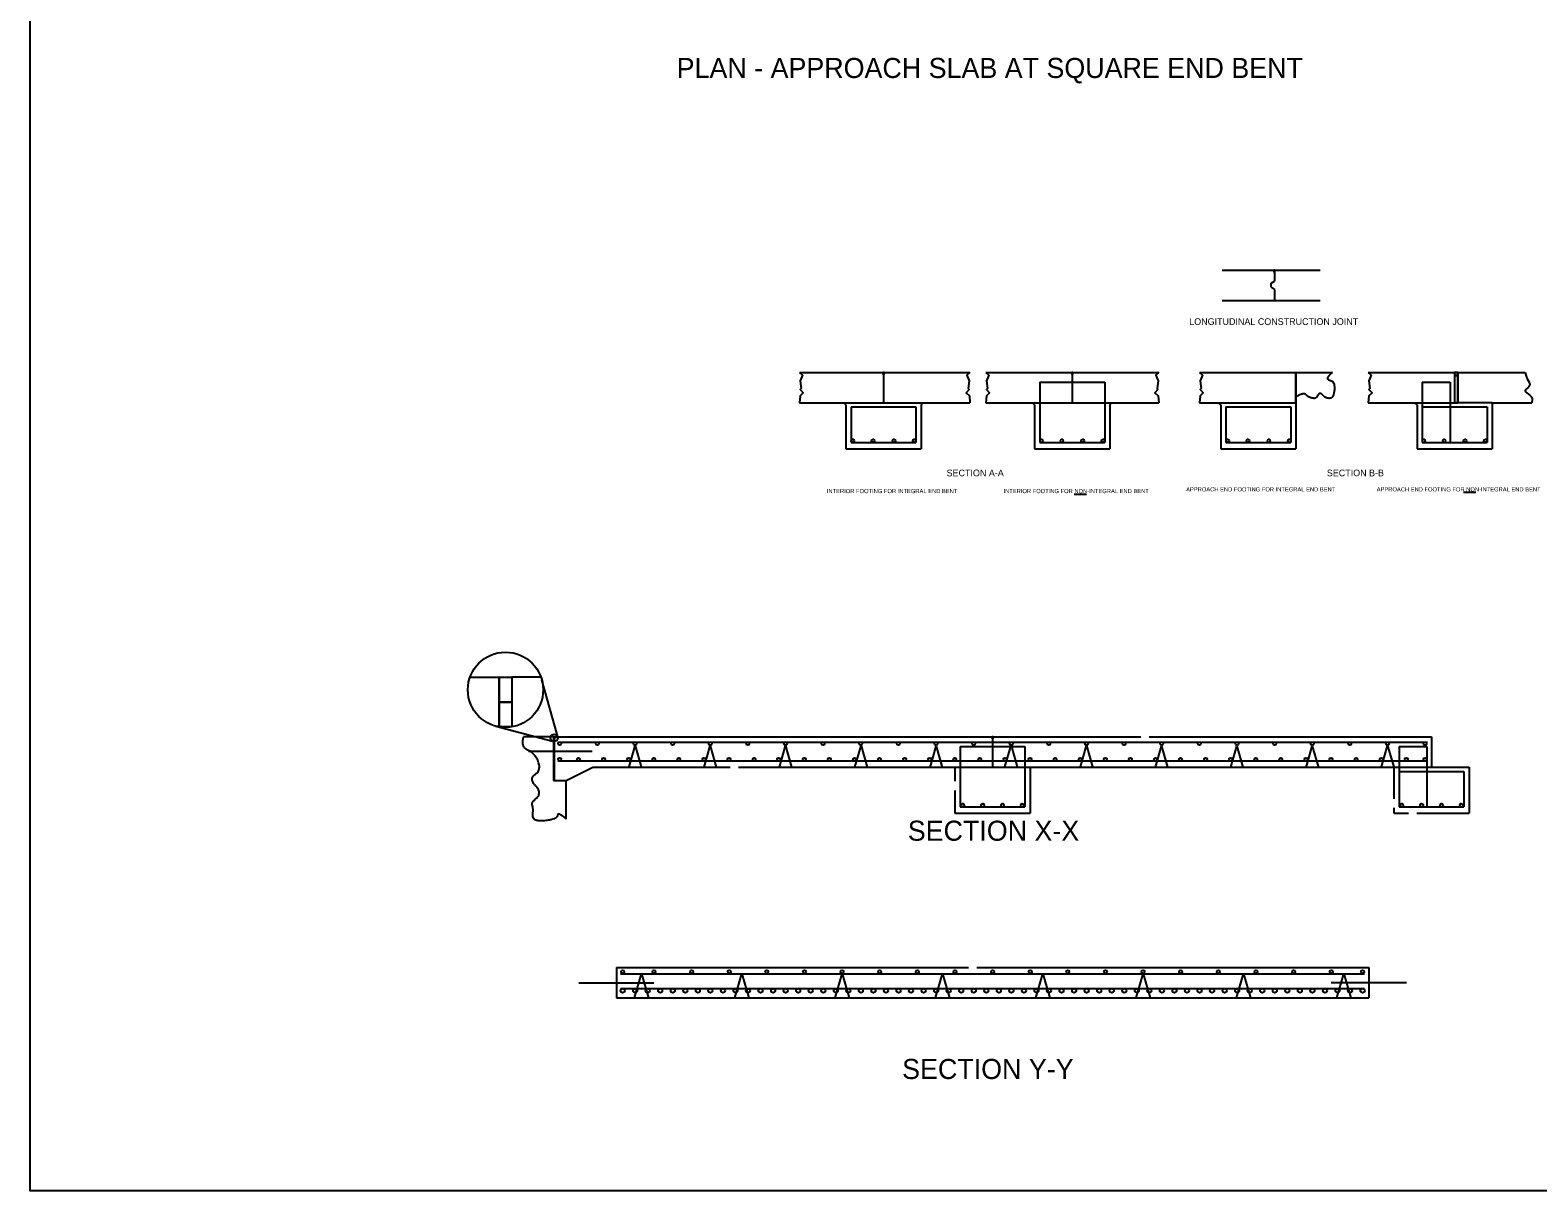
# Model space of a CAD drawing. Extents: x 1531 to 2925, y 1224 to 1658.
# Drawn here: x 2396.3 to 2456.4, y 1330.2 to 1376.5 of the extents above; entities that cross this region are included whole.
import ezdxf

# ---------------------------------------------------------------- set-up
doc = ezdxf.new("R2010")
doc.units = 0
for name, color, linetype in [('B_Boring Annot', 7, 'Continuous'), ('BD-EXIST-COSS', 7, 'Continuous'), ('BD-PROP-COSS', 7, 'Continuous'), ('BD-PROP-OSB', 7, 'Continuous'), ('D_FEMA A', 7, 'Continuous'), ('R_Anno_Text', 7, 'Continuous'), ('R_Draft', 7, 'Continuous'), ('R_Horz Alg', 7, 'Continuous'), ('R_Road Edge of Shoulder', 7, 'Continuous'), ('R_Road Edge of Travel', 7, 'Continuous'), ('R_ROW', 7, 'Continuous'), ('R_Survey Control', 7, 'Continuous'), ('R_Wall', 7, 'Continuous'), ('S_GAS_UTILITIES', 7, 'Continuous')]:
    doc.layers.add(name, color=color, linetype=linetype)

msp = doc.modelspace()

# ---------------------------------------------------------------- linework, layer by layer
at = {"layer": 'B_Boring Annot'}
for p, q in [((2413.853, 1350.708), (2415.017, 1350.708)), ((2415.017, 1350.708), (2415.017, 1348.729))]:
    msp.add_line(p, q, dxfattribs=at)
at = {"layer": 'BD-EXIST-COSS'}
for p, q in [((2436.57, 1362.472), (2439.154, 1362.472)), ((2436.57, 1362.472), (2436.57, 1360.068)), ((2439.154, 1362.472), (2439.154, 1360.068)), ((2451.815, 1362.472), (2452.925, 1362.472)), ((2451.815, 1362.472), (2451.815, 1360.066)), ((2452.925, 1362.472), (2452.925, 1360.066)), ((2429.044, 1361.485), (2431.628, 1361.485)), ((2429.044, 1361.485), (2429.044, 1360.068)), ((2431.628, 1361.485), (2431.628, 1360.068)), ((2443.99, 1361.485), (2446.573, 1361.485)), ((2443.99, 1361.485), (2443.99, 1360.068)), ((2446.573, 1361.485), (2446.573, 1360.068)), ((2451.815, 1361.485), (2454.398, 1361.485)), ((2451.815, 1361.485), (2451.815, 1360.068)), ((2454.398, 1361.485), (2454.398, 1360.068)), ((2429.044, 1360.068), (2431.628, 1360.068)), ((2436.57, 1360.068), (2439.154, 1360.068)), ((2443.99, 1360.068), (2446.573, 1360.068)), ((2451.815, 1360.068), (2454.398, 1360.068)), ((2417.352, 1348.123), (2452.019, 1348.123)), ((2433.394, 1347.943), (2435.977, 1347.943)), ((2433.394, 1347.943), (2433.394, 1345.539)), ((2435.977, 1347.943), (2435.977, 1345.539)), ((2450.894, 1347.943), (2452.004, 1347.943)), ((2450.894, 1347.943), (2450.894, 1345.537)), ((2452.004, 1347.943), (2452.004, 1345.537)), ((2417.352, 1347.373), (2452.019, 1347.373)), ((2450.894, 1346.956), (2453.477, 1346.956)), ((2453.477, 1346.956), (2453.477, 1345.539)), ((2433.394, 1345.539), (2435.977, 1345.539)), ((2450.894, 1345.539), (2453.477, 1345.539)), ((2419.852, 1338.88), (2449.519, 1338.88)), ((2418.186, 1338.526), (2421.186, 1338.526)), ((2419.852, 1338.298), (2449.519, 1338.298)), ((2451.186, 1338.526), (2448.186, 1338.526))]:
    msp.add_line(p, q, dxfattribs=at)
for centre, radius in [((2429.109, 1360.134), 0.0625), ((2429.919, 1360.134), 0.0625), ((2430.753, 1360.134), 0.0625), ((2431.563, 1360.134), 0.0625), ((2436.635, 1360.134), 0.0625), ((2437.445, 1360.134), 0.0625), ((2438.279, 1360.134), 0.0625), ((2439.089, 1360.134), 0.0625), ((2444.054, 1360.134), 0.0625), ((2444.865, 1360.134), 0.0625), ((2445.698, 1360.134), 0.0625), ((2446.508, 1360.134), 0.0625), ((2451.88, 1360.134), 0.0625), ((2452.69, 1360.134), 0.0625), ((2453.523, 1360.134), 0.0625), ((2454.334, 1360.134), 0.0625), ((2417.429, 1348.06), 0.063), ((2418.929, 1348.06), 0.063), ((2420.429, 1348.06), 0.063), ((2421.929, 1348.06), 0.063), ((2423.429, 1348.06), 0.063), ((2424.929, 1348.06), 0.063), ((2426.429, 1348.06), 0.063), ((2427.929, 1348.06), 0.063), ((2429.429, 1348.06), 0.063), ((2430.929, 1348.06), 0.063), ((2432.429, 1348.06), 0.063), ((2433.929, 1348.06), 0.063), ((2435.429, 1348.06), 0.063), ((2436.929, 1348.06), 0.063), ((2438.429, 1348.06), 0.063), ((2439.929, 1348.06), 0.063), ((2441.429, 1348.06), 0.063), ((2442.929, 1348.06), 0.063), ((2444.429, 1348.06), 0.063), ((2445.929, 1348.06), 0.063), ((2447.429, 1348.06), 0.063), ((2448.929, 1348.06), 0.063), ((2450.429, 1348.06), 0.063), ((2451.929, 1348.06), 0.063), ((2417.429, 1347.436), 0.063), ((2418.179, 1347.436), 0.063), ((2419.179, 1347.436), 0.063), ((2420.179, 1347.436), 0.063), ((2421.179, 1347.436), 0.063), ((2422.179, 1347.436), 0.063), ((2423.179, 1347.436), 0.063), ((2424.179, 1347.436), 0.063), ((2425.179, 1347.436), 0.063), ((2426.156, 1347.436), 0.063), ((2427.179, 1347.436), 0.063), ((2428.179, 1347.436), 0.063), ((2429.179, 1347.436), 0.063), ((2430.179, 1347.436), 0.063), ((2431.179, 1347.436), 0.063), ((2432.179, 1347.436), 0.063), ((2433.179, 1347.436), 0.063), ((2434.179, 1347.436), 0.063), ((2435.179, 1347.436), 0.063), ((2436.179, 1347.436), 0.063), ((2437.179, 1347.436), 0.063), ((2438.179, 1347.436), 0.063), ((2439.179, 1347.436), 0.063), ((2440.179, 1347.436), 0.063), ((2441.179, 1347.436), 0.063), ((2442.179, 1347.436), 0.063), ((2443.179, 1347.436), 0.063), ((2444.179, 1347.436), 0.063), ((2445.179, 1347.436), 0.063), ((2446.179, 1347.436), 0.063), ((2447.179, 1347.436), 0.063), ((2448.179, 1347.436), 0.063), ((2449.179, 1347.436), 0.063), ((2450.179, 1347.436), 0.063), ((2451.179, 1347.436), 0.063), ((2451.929, 1347.436), 0.063), ((2433.501, 1345.605), 0.0625), ((2434.291, 1345.605), 0.0625), ((2435.08, 1345.605), 0.0625), ((2435.87, 1345.605), 0.0625), ((2451.001, 1345.605), 0.0625), ((2451.791, 1345.605), 0.0625), ((2452.58, 1345.605), 0.0625), ((2453.37, 1345.605), 0.0625), ((2419.936, 1338.965), 0.063), ((2421.186, 1338.965), 0.063), ((2422.686, 1338.965), 0.063), ((2424.186, 1338.965), 0.063), ((2425.686, 1338.965), 0.063), ((2427.186, 1338.965), 0.063), ((2428.686, 1338.965), 0.063), ((2430.186, 1338.965), 0.063), ((2431.686, 1338.965), 0.063), ((2433.186, 1338.965), 0.063), ((2434.686, 1338.965), 0.063), ((2436.186, 1338.965), 0.063), ((2437.686, 1338.965), 0.063), ((2439.186, 1338.965), 0.063), ((2440.686, 1338.965), 0.063), ((2442.186, 1338.965), 0.063), ((2443.686, 1338.965), 0.063), ((2445.186, 1338.965), 0.063), ((2446.686, 1338.965), 0.063), ((2448.186, 1338.965), 0.063), ((2449.436, 1338.965), 0.063), ((2419.936, 1338.214), 0.0833), ((2420.436, 1338.214), 0.0833), ((2420.936, 1338.214), 0.0833), ((2421.436, 1338.214), 0.0833), ((2421.936, 1338.214), 0.0833), ((2422.436, 1338.214), 0.0833), ((2422.936, 1338.214), 0.0833), ((2423.436, 1338.214), 0.0833), ((2423.936, 1338.214), 0.0833), ((2424.436, 1338.214), 0.0833), ((2424.936, 1338.214), 0.0833), ((2425.436, 1338.214), 0.0833), ((2425.936, 1338.214), 0.0833), ((2426.436, 1338.214), 0.0833), ((2426.936, 1338.214), 0.0833), ((2427.436, 1338.214), 0.0833), ((2427.936, 1338.214), 0.0833), ((2428.436, 1338.214), 0.0833), ((2428.936, 1338.214), 0.0833), ((2429.436, 1338.214), 0.0833), ((2429.936, 1338.214), 0.0833), ((2430.436, 1338.214), 0.0833), ((2430.936, 1338.214), 0.0833), ((2431.436, 1338.214), 0.0833), ((2431.936, 1338.214), 0.0833), ((2432.436, 1338.214), 0.0833), ((2432.936, 1338.214), 0.0833), ((2433.436, 1338.214), 0.0833), ((2433.936, 1338.214), 0.0833), ((2434.436, 1338.214), 0.0833), ((2434.936, 1338.214), 0.0833), ((2435.436, 1338.214), 0.0833), ((2435.936, 1338.214), 0.0833), ((2436.436, 1338.214), 0.0833), ((2436.936, 1338.214), 0.0833), ((2437.436, 1338.214), 0.0833), ((2437.936, 1338.214), 0.0833), ((2438.436, 1338.214), 0.0833), ((2438.936, 1338.214), 0.0833), ((2439.436, 1338.214), 0.0833), ((2439.936, 1338.214), 0.0833), ((2440.436, 1338.214), 0.0833), ((2440.936, 1338.214), 0.0833), ((2441.436, 1338.214), 0.0833), ((2441.936, 1338.214), 0.0833), ((2442.436, 1338.214), 0.0833), ((2442.936, 1338.214), 0.0833), ((2443.436, 1338.214), 0.0833), ((2443.936, 1338.214), 0.0833), ((2444.436, 1338.214), 0.0833), ((2444.936, 1338.214), 0.0833), ((2445.436, 1338.214), 0.0833), ((2445.936, 1338.214), 0.0833), ((2446.436, 1338.214), 0.0833), ((2446.936, 1338.214), 0.0833), ((2447.436, 1338.214), 0.0833), ((2447.936, 1338.214), 0.0833), ((2448.436, 1338.214), 0.0833), ((2448.936, 1338.214), 0.0833), ((2449.436, 1338.214), 0.0833)]:
    msp.add_circle(centre, radius, dxfattribs=at)
at = {"layer": 'BD-PROP-COSS'}
for p, q in [((2445.897, 1366.944), (2445.897, 1366.86)), ((2445.939, 1366.944), (2445.897, 1366.944)), ((2445.897, 1366.86), (2445.939, 1366.86)), ((2445.939, 1366.86), (2445.939, 1366.944)), ((2430.315, 1362.86), (2430.315, 1362.776)), ((2430.357, 1362.86), (2430.315, 1362.86)), ((2430.315, 1362.776), (2430.357, 1362.776)), ((2430.357, 1362.776), (2430.357, 1362.86)), ((2437.841, 1362.86), (2437.841, 1362.776)), ((2437.883, 1362.86), (2437.841, 1362.86)), ((2437.841, 1362.776), (2437.883, 1362.776)), ((2437.883, 1362.776), (2437.883, 1362.86)), ((2415.017, 1350.708), (2415.517, 1350.708)), ((2417.227, 1348.331), (2417.186, 1348.331)), ((2434.665, 1348.331), (2434.665, 1348.248)), ((2434.707, 1348.331), (2434.665, 1348.331)), ((2434.665, 1348.248), (2434.707, 1348.248)), ((2434.686, 1348.331), (2434.686, 1347.123)), ((2434.707, 1348.248), (2434.707, 1348.331))]:
    msp.add_line(p, q, dxfattribs=at)
at = {"layer": 'BD-PROP-OSB'}
for p, q in [((2415.017, 1348.729), (2415.017, 1349.708)), ((2415.017, 1349.708), (2415.517, 1349.708)), ((2415.517, 1349.708), (2415.517, 1348.729)), ((2415.517, 1348.729), (2415.017, 1348.729)), ((2417.227, 1348.248), (2417.186, 1348.248)), ((2417.186, 1348.248), (2417.186, 1348.248)), ((2417.186, 1348.248), (2417.186, 1346.593)), ((2417.227, 1346.593), (2417.227, 1348.248)), ((2417.186, 1346.593), (2417.227, 1346.593)), ((2417.186, 1346.593), (2417.186, 1346.593))]:
    msp.add_line(p, q, dxfattribs=at)
at = {"layer": 'D_FEMA A'}
for p, q in [((2420.191, 1347.134), (2420.435, 1347.979)), ((2420.435, 1347.979), (2420.678, 1347.134)), ((2423.186, 1347.127), (2423.429, 1347.971)), ((2423.429, 1347.971), (2423.672, 1347.127)), ((2426.187, 1347.123), (2426.43, 1347.967)), ((2426.43, 1347.967), (2426.673, 1347.123)), ((2429.2, 1347.129), (2429.443, 1347.973)), ((2429.443, 1347.973), (2429.686, 1347.129)), ((2432.193, 1347.113), (2432.437, 1347.958)), ((2432.437, 1347.958), (2432.68, 1347.113)), ((2435.178, 1347.137), (2435.421, 1347.981)), ((2435.421, 1347.981), (2435.665, 1347.137)), ((2438.186, 1347.139), (2438.429, 1347.983)), ((2438.429, 1347.983), (2438.673, 1347.139)), ((2441.176, 1347.118), (2441.419, 1347.962)), ((2441.419, 1347.962), (2441.662, 1347.118)), ((2444.181, 1347.12), (2444.424, 1347.964)), ((2444.424, 1347.964), (2444.667, 1347.12)), ((2447.187, 1347.109), (2447.43, 1347.954)), ((2447.43, 1347.954), (2447.673, 1347.109)), ((2450.191, 1347.13), (2450.434, 1347.974)), ((2450.434, 1347.974), (2450.677, 1347.13)), ((2420.406, 1337.922), (2420.689, 1338.88)), ((2420.689, 1338.88), (2420.972, 1337.922)), ((2424.406, 1337.922), (2424.689, 1338.88)), ((2424.689, 1338.88), (2424.972, 1337.922)), ((2428.406, 1337.922), (2428.689, 1338.88)), ((2428.689, 1338.88), (2428.972, 1337.922)), ((2432.406, 1337.922), (2432.689, 1338.88)), ((2432.406, 1337.922), (2432.689, 1338.88)), ((2432.689, 1338.88), (2432.972, 1337.922)), ((2432.689, 1338.88), (2432.972, 1337.922)), ((2436.406, 1337.922), (2436.689, 1338.88)), ((2436.689, 1338.88), (2436.972, 1337.922)), ((2440.406, 1337.922), (2440.689, 1338.88)), ((2440.689, 1338.88), (2440.972, 1337.922)), ((2444.406, 1337.922), (2444.689, 1338.88)), ((2444.689, 1338.88), (2444.972, 1337.922)), ((2448.406, 1337.922), (2448.689, 1338.88)), ((2448.689, 1338.88), (2448.972, 1337.922))]:
    msp.add_line(p, q, dxfattribs=at)
at = {"layer": 'R_Anno_Text'}
msp.add_line((2416.188, 1347.757), (2418.727, 1347.757), dxfattribs=at)
at = {"layer": 'R_Draft'}
for p, q in [((2443.834, 1366.944), (2447.751, 1366.944)), ((2445.918, 1366.86), (2445.918, 1366.507)), ((2445.793, 1366.424), (2445.918, 1366.507)), ((2445.793, 1366.257), (2445.793, 1366.424)), ((2445.793, 1366.257), (2445.918, 1366.174)), ((2443.834, 1365.735), (2447.751, 1365.735)), ((2445.918, 1366.174), (2445.918, 1365.735)), ((2426.988, 1362.86), (2433.783, 1362.86)), ((2426.988, 1362.86), (2433.783, 1362.86)), ((2430.336, 1362.86), (2430.336, 1361.651)), ((2434.415, 1362.86), (2441.309, 1362.86)), ((2437.385, 1362.86), (2441.309, 1362.86)), ((2437.862, 1362.86), (2437.862, 1361.651)), ((2442.933, 1362.86), (2446.781, 1362.86)), ((2446.781, 1362.86), (2446.781, 1361.651)), ((2446.781, 1361.651), (2446.781, 1362.86)), ((2446.781, 1362.86), (2448.233, 1362.86)), ((2449.66, 1362.86), (2453.107, 1362.86)), ((2449.66, 1362.86), (2453.107, 1362.86)), ((2453.107, 1362.86), (2453.107, 1361.651)), ((2453.107, 1362.86), (2455.914, 1362.86)), ((2453.232, 1362.86), (2453.232, 1361.651)), ((2426.988, 1361.651), (2428.753, 1361.651)), ((2428.836, 1361.568), (2428.753, 1361.651)), ((2428.753, 1361.651), (2431.919, 1361.651)), ((2428.836, 1361.568), (2428.836, 1359.818)), ((2431.836, 1361.568), (2431.919, 1361.651)), ((2431.836, 1361.568), (2431.836, 1359.818)), ((2431.919, 1361.651), (2433.783, 1361.651)), ((2434.415, 1361.651), (2436.279, 1361.651)), ((2436.362, 1361.568), (2436.279, 1361.651)), ((2436.279, 1361.651), (2439.445, 1361.651)), ((2436.362, 1361.568), (2436.362, 1359.818)), ((2439.362, 1361.568), (2439.445, 1361.651)), ((2439.362, 1361.568), (2439.362, 1359.818)), ((2439.445, 1361.651), (2441.309, 1361.651)), ((2442.933, 1361.651), (2443.698, 1361.651)), ((2443.781, 1361.568), (2443.698, 1361.651)), ((2443.698, 1361.651), (2446.781, 1361.651)), ((2443.781, 1361.568), (2443.781, 1359.818)), ((2446.781, 1361.651), (2446.781, 1359.818)), ((2449.66, 1361.651), (2451.523, 1361.651)), ((2451.523, 1361.651), (2453.107, 1361.651)), ((2451.607, 1361.568), (2451.523, 1361.651)), ((2451.607, 1361.568), (2451.607, 1359.818)), ((2454.607, 1361.651), (2453.107, 1361.651)), ((2454.607, 1361.651), (2454.607, 1359.818)), ((2454.607, 1361.651), (2456.182, 1361.651)), ((2428.836, 1359.818), (2431.836, 1359.818)), ((2436.362, 1359.818), (2439.362, 1359.818)), ((2443.781, 1359.818), (2446.781, 1359.818)), ((2451.607, 1359.818), (2454.607, 1359.818)), ((2415.017, 1349.708), (2415.017, 1350.708)), ((2415.017, 1350.708), (2415.517, 1350.708)), ((2415.517, 1350.708), (2415.517, 1350.708)), ((2415.517, 1350.708), (2415.517, 1349.708)), ((2415.517, 1349.708), (2415.017, 1349.708)), ((2415.517, 1349.708), (2415.517, 1349.708)), ((2417.186, 1348.331), (2440.591, 1348.331)), ((2417.186, 1348.331), (2417.186, 1348.331)), ((2417.186, 1348.331), (2417.186, 1348.248)), ((2417.227, 1348.331), (2417.186, 1348.331)), ((2417.186, 1348.248), (2417.186, 1348.248)), ((2417.186, 1348.248), (2417.227, 1348.248)), ((2417.227, 1348.331), (2417.227, 1348.248)), ((2417.227, 1348.248), (2417.227, 1348.331)), ((2440.924, 1348.331), (2452.186, 1348.331)), ((2452.186, 1348.331), (2452.186, 1347.123)), ((2417.686, 1346.593), (2418.746, 1347.123)), ((2418.746, 1347.123), (2424.218, 1347.123)), ((2424.551, 1347.123), (2453.686, 1347.123)), ((2433.186, 1347.123), (2433.186, 1346.561)), ((2436.186, 1347.123), (2436.186, 1345.289)), ((2450.686, 1347.123), (2450.686, 1345.866)), ((2453.686, 1347.123), (2453.686, 1345.289)), ((2433.186, 1346.198), (2433.186, 1345.289)), ((2433.186, 1345.289), (2436.186, 1345.289)), ((2450.686, 1345.504), (2450.686, 1345.289)), ((2450.686, 1345.289), (2451.261, 1345.289)), ((2451.594, 1345.289), (2453.686, 1345.289)), ((2419.686, 1339.13), (2433.723, 1339.13)), ((2419.686, 1339.13), (2419.686, 1337.922)), ((2434.057, 1339.13), (2449.686, 1339.13)), ((2449.686, 1339.13), (2449.686, 1337.922)), ((2419.686, 1337.922), (2449.686, 1337.922))]:
    msp.add_line(p, q, dxfattribs=at)
for points in [[(2426.988, 1362.86), (2427.108, 1362.753), (2427.014, 1362.523), (2427.052, 1362.227), (2427.018, 1362.177), (2427.14, 1362.049), (2427.012, 1361.928), (2426.988, 1361.651)], [(2433.783, 1362.86), (2433.662, 1362.753), (2433.757, 1362.523), (2433.718, 1362.227), (2433.752, 1362.177), (2433.631, 1362.049), (2433.759, 1361.928), (2433.783, 1361.651)], [(2434.415, 1362.86), (2434.536, 1362.753), (2434.441, 1362.523), (2434.48, 1362.227), (2434.446, 1362.177), (2434.567, 1362.049), (2434.44, 1361.928), (2434.415, 1361.651)], [(2441.309, 1362.86), (2441.189, 1362.753), (2441.283, 1362.523), (2441.244, 1362.227), (2441.278, 1362.177), (2441.157, 1362.049), (2441.285, 1361.928), (2441.309, 1361.651)], [(2442.933, 1362.86), (2443.053, 1362.753), (2442.959, 1362.523), (2442.998, 1362.227), (2442.963, 1362.177), (2443.085, 1362.049), (2442.957, 1361.928), (2442.933, 1361.651)], [(2449.66, 1362.86), (2449.78, 1362.753), (2449.686, 1362.523), (2449.725, 1362.227), (2449.691, 1362.177), (2449.812, 1362.049), (2449.684, 1361.928), (2449.66, 1361.651)]]:
    msp.add_lwpolyline(points, dxfattribs=at)
for points, degree in [([(2448.233, 1362.86), (2448.039, 1362.696), (2448.039, 1362.571), (2448.341, 1362.483), (2448.278, 1361.828), (2447.963, 1361.828), (2447.753, 1362.062), (2447.655, 1361.964), (2447.568, 1361.801), (2447.264, 1361.881), (2447.092, 1362.067), (2446.781, 1361.892)], 2), ([(2455.914, 1362.86), (2455.969, 1362.631), (2456.111, 1362.473), (2456.111, 1362.276), (2455.817, 1362.129), (2456.139, 1361.958), (2456.231, 1361.826), (2456.182, 1361.651)], 3)]:
    msp.add_open_spline(points, degree=degree, dxfattribs=at)
at = {"layer": 'R_Horz Alg'}
for p, q in [((2437.942, 1358.013), (2438.435, 1358.013)), ((2453.453, 1358.082), (2453.946, 1358.082))]:
    msp.add_line(p, q, dxfattribs=at)
at = {"layer": 'R_Road Edge of Shoulder'}
for p, q in [((2417.186, 1348.331), (2415.987, 1348.331)), ((2417.686, 1345.051), (2417.686, 1346.593))]:
    msp.add_line(p, q, dxfattribs=at)
msp.add_open_spline([(2417.686, 1345.051), (2417.346, 1345.351), (2417.334, 1345.043), (2416.327, 1344.93), (2416.383, 1345.506), (2416.282, 1345.696), (2416.733, 1346.098), (2416.2, 1346.66), (2416.705, 1347.006), (2416.438, 1347.681), (2415.883, 1347.913), (2415.987, 1348.331)], degree=2, dxfattribs=at)
at = {"layer": 'R_Road Edge of Travel'}
for p, q in [((2416.681, 1350.708), (2415.517, 1350.708)), ((2415.517, 1350.708), (2415.517, 1348.729)), ((2417.186, 1348.331), (2417.186, 1346.593)), ((2417.186, 1346.593), (2417.686, 1346.593))]:
    msp.add_line(p, q, dxfattribs=at)
at = {"layer": 'R_Survey Control'}
for p, q in [((2417.348, 1348.329), (2416.712, 1350.61)), ((2414.881, 1348.759), (2417.146, 1348.156))]:
    msp.add_line(p, q, dxfattribs=at)
for centre, radius in [((2415.267, 1350.208), 1.5), ((2417.207, 1348.289), 0.147)]:
    msp.add_circle(centre, radius, dxfattribs=at)
at = {"layer": 'R_Wall'}
msp.add_lwpolyline([(2396.317, 1427.125), (2541.534, 1427.125), (2541.534, 1330.23), (2396.317, 1330.23)], close=True, dxfattribs=at)
at = {"layer": 'S_GAS_UTILITIES'}
for p, q in [((2453.232, 1362.86), (2453.107, 1362.86)), ((2453.107, 1362.86), (2453.107, 1362.735)), ((2453.107, 1362.735), (2453.107, 1361.651)), ((2453.232, 1362.735), (2453.107, 1362.735)), ((2453.107, 1362.735), (2453.232, 1362.735)), ((2453.232, 1362.735), (2453.232, 1362.86)), ((2453.232, 1361.651), (2453.232, 1362.735)), ((2453.107, 1361.651), (2453.232, 1361.651))]:
    msp.add_line(p, q, dxfattribs=at)

# ---------------------------------------------------------------- texts
at = {"layer": 'R_Horz Alg'}
for s, p in [('INTERIOR FOOTING FOR INTEGRAL END BENT', (2428.078, 1358.048)), ('INTERIOR FOOTING FOR NON-INTEGRAL END BENT', (2435.121, 1358.048)), ('APPROACH END FOOTING FOR INTEGRAL END BENT', (2442.401, 1358.117)), ('APPROACH END FOOTING FOR NON-INTEGRAL END BENT', (2449.999, 1358.117))]:
    msp.add_text(s, height=0.16667, dxfattribs=at).set_placement(p)
at = {"layer": 'R_ROW'}
for s, height, p in [('PLAN - APPROACH SLAB AT SQUARE END BENT', 0.8, (2422.09, 1374.601)), ('LONGITUDINAL CONSTRUCTION JOINT', 0.26667, (2442.526, 1364.756)), ('SECTION A-A', 0.26667, (2432.853, 1358.721)), ('SECTION B-B', 0.26667, (2448.011, 1358.721)), ('SECTION X-X', 0.8, (2431.304, 1344.189)), ('SECTION Y-Y', 0.8, (2431.08, 1334.689))]:
    msp.add_text(s, height=height, dxfattribs=at).set_placement(p)

doc.saveas('drawing.dxf')
